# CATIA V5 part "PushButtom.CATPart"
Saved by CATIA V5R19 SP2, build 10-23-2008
Part number: PushButtom
Revision: ANY
Definition: UNKNOWN
Nomenclature: PushButtom
Source: Unknown
Bounding box of the stored display mesh (mm): x 0 to 4, y -6 to 6, z -6 to 6
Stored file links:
  Z:\fausse table rondelle-20220905T211342Z-001\fausse table rondelle\PushButtom.CATPart
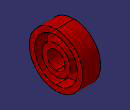
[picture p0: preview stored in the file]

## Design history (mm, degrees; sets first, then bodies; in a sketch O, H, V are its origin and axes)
AxisSystem1: origin (0, 0, 0), X (1, 0, 0), Y (0, 1, 0), Z (0, 0, 1)
Body1 "Rotation1" (main body)
  Solid1: solid without history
